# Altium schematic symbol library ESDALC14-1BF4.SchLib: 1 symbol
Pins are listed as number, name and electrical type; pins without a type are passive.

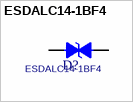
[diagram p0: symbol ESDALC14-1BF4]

## ESDALC14-1BF4
designator D?
footprint ST_0201B-F4
pins: 1, 2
